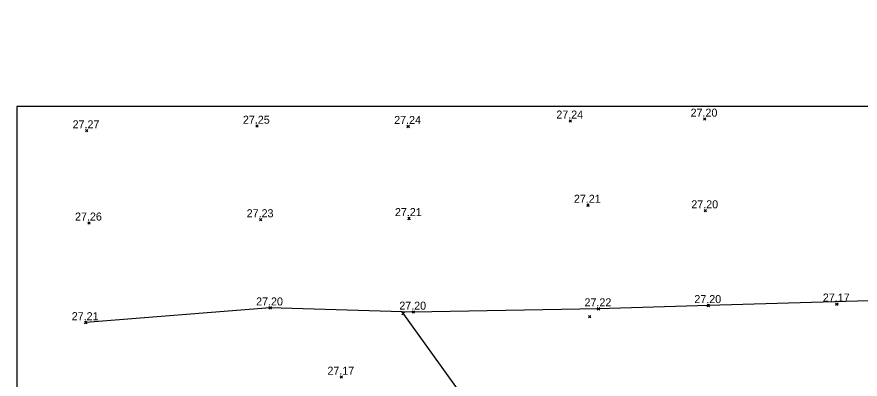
# Model space of a CAD drawing. Extents: x 37864 to 38032, y 453991 to 454052.
# Drawn here: x 37864.06 to 37894.08, y 454038.52 to 454051.41 of the extents above; entities that cross this region are included whole.
import ezdxf

# ---------------------------------------------------------------- set-up
doc = ezdxf.new("R2010")
doc.units = 0
for name, color, linetype in [('DH_CALCUL SURFACE-TEXTE', 7, 'Continuous'), ('GO_POTEAU', 7, 'Continuous'), ('SO_SANITAIRE DETAILLE', 7, 'Continuous')]:
    doc.layers.add(name, color=color, linetype=linetype)

# ---------------------------------------------------------------- blocks, each defined once
blk = doc.blocks.new('POINT_DISPLAY')
for p, q in [((-0.04375, -0.04375), (0.04375, 0.04375)), ((-0.04375, 0.04375), (0.04375, -0.04375))]:
    blk.add_line(p, q)
blk = doc.blocks.new('POINTCOT')
blk.add_blockref('POINT_DISPLAY', (0, 0))

msp = doc.modelspace()

# ---------------------------------------------------------------- linework, layer by layer
at = {"layer": 'DEFPOINTS'}
msp.add_lwpolyline([(37864.064, 453990.816), (37946.064, 453990.816), (37946.064, 454048.216), (37864.064, 454048.216)], close=True, dxfattribs=at)
at = {"layer": 'SO_SANITAIRE DETAILLE'}
for points in [[(37931.461, 454051.412), (37931.46, 454048.283), (37931.063, 454042.806), (37929.02, 454042.628), (37924.438, 454042.4), (37918.697, 454042.102), (37913.082, 454041.936), (37907.417, 454041.715), (37901.195, 454041.497), (37895.602, 454041.336), (37888.675, 454041.141), (37884.765, 454041.024), (37878.173, 454040.907), (37873.078, 454041.057), (37866.515, 454040.532)], [(37877.767, 454040.919), (37880.278, 454037.408), (37879.922, 454031.271), (37881.601, 454024.153), (37881.601, 454024.153), (37881.601, 454024.153), (37881.675, 454023.821), (37881.781, 454022.267), (37881.901, 454020.769), (37881.927, 454020.39), (37882.008, 454019.105), (37882.114, 454018.134), (37882.561, 454015.43), (37882.656, 454013.593), (37882.577, 454012.12), (37882.592, 454010.925), (37882.785, 454009.367), (37882.96, 454007.587), (37882.985, 454004.477)]]:
    msp.add_lwpolyline(points, dxfattribs=at)

# ---------------------------------------------------------------- block references
at = {"layer": 'DH_CALCUL SURFACE-TEXTE', "rotation": 2.2526485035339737e-05}
for p in [(37883.762, 454047.709), (37888.54, 454047.776), (37872.608, 454047.524), (37877.992, 454047.516), (37866.546, 454047.361), (37884.388, 454044.711), (37888.566, 454044.515), (37872.742, 454044.196), (37878.018, 454044.237), (37866.633, 454044.078), (37888.675, 454041.141), (37893.248, 454041.195), (37873.078, 454041.057), (37877.814, 454040.855), (37878.173, 454040.907), (37884.765, 454041.024), (37866.515, 454040.532), (37884.45, 454040.743), (37875.615, 454038.591)]:
    msp.add_blockref('POINTCOT', p, dxfattribs=at)

# ---------------------------------------------------------------- texts
at = {"layer": 'GO_POTEAU'}
for s, p in [('27.24', (37883.264, 454047.793)), ('27.20', (37888.042, 454047.86)), ('27.25', (37872.11, 454047.608)), ('27.24', (37877.494, 454047.6)), ('27.27', (37866.048, 454047.445)), ('27.21', (37883.89, 454044.795)), ('27.20', (37888.068, 454044.598)), ('27.26', (37866.135, 454044.162)), ('27.23', (37872.244, 454044.28)), ('27.21', (37877.52, 454044.321)), ('27.20', (37888.177, 454041.225)), ('27.17', (37892.75, 454041.279)), ('27.20', (37872.58, 454041.141)), ('27.20', (37877.675, 454040.991)), ('27.22', (37884.267, 454041.108)), ('27.21', (37866.017, 454040.616)), ('27.17', (37875.117, 454038.675))]:
    msp.add_text(s, height=0.285, rotation=0, dxfattribs=at).set_placement(p)

doc.saveas('drawing.dxf')
